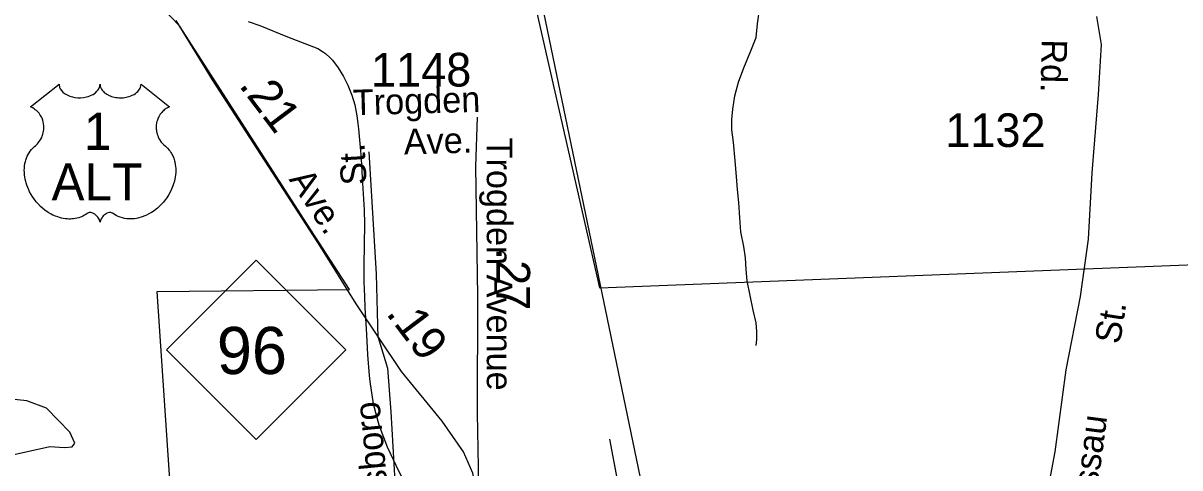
# Model space of a CAD drawing. Extents: x 2126262 to 2293712, y 749403 to 919119.
# Drawn here: x 2152197 to 2156490, y 829545 to 831196 of the extents above; entities that cross this region are included whole.
import ezdxf

# ---------------------------------------------------------------- set-up
doc = ezdxf.new("R2010")
doc.units = 0
for name, color, linetype in [('Exist Boundary Political City Limit New', 7, 'Continuous'), ('Exist Hydrographic Misc Water Feature', 7, 'Continuous'), ('Exist Hydrographic Pond Under 1500 Sq Ft', 7, 'Continuous'), ('Exist Railroad Mainline', 7, 'Continuous'), ('Exist Road Non-System Type 51', 7, 'Continuous'), ('Exist Road Non-System Type 51 Label', 7, 'Continuous'), ('Exist Road Primary NC Shield CELL', 7, 'Continuous'), ('Exist Road Primary NC Shield Number Label', 7, 'Continuous'), ('Exist Road Primary US Attributed', 7, 'Continuous'), ('Exist Road Primary US Label', 7, 'Continuous'), ('Exist Road Primary US Mileage Hundredths English Label', 7, 'Continuous'), ('Exist Road Primary US Shield CELL', 7, 'Continuous'), ('Exist Road Primary US Shield Number Label', 7, 'Continuous'), ('Exist Road Secondary Mileage Hundredths English Label', 7, 'Continuous'), ('Exist Road Secondary Type 51 Attributed', 7, 'Continuous'), ('Exist Road Secondary Type 51 Label', 7, 'Continuous'), ('Exist Road Secondary Type 51 Number Label', 7, 'Continuous'), ('Map Preparation Boundary City Limit Buffer Line', 7, 'Continuous')]:
    doc.layers.add(name, color=color, linetype=linetype)

msp = doc.modelspace()

# ---------------------------------------------------------------- linework, layer by layer
at = {"layer": 'Exist Boundary Political City Limit New'}
for points in [[(2153914.5, 832061.1), (2154336.2, 830213.6), (2156611.8, 830301.9), (2156864.5, 826396)], [(2152602.5, 827929.4), (2152838, 827985.8), (2152766.8, 829114.4), (2152693.8, 830199.1), (2153408, 830206.8), (2153250.2, 830449.8), (2152776.5, 831185.2), (2152645.8, 831322.7)]]:
    msp.add_lwpolyline(points, dxfattribs=at)
at = {"layer": 'Exist Hydrographic Misc Water Feature'}
for points in [[(2154917.4, 829998.9), (2154919, 830020.9), (2154919, 830050.9), (2154916.7, 830082.9), (2154906.5, 830130.8), (2154894.4, 830184.7), (2154883.7, 830238.7), (2154879.6, 830280.6), (2154877.4, 830324.6), (2154871, 830366.6), (2154860.8, 830420.5), (2154856.5, 830472.5), (2154852.4, 830530.5), (2154848.1, 830578.4), (2154843.7, 830626.4), (2154839.2, 830684.3), (2154833.1, 830754.3), (2154826.7, 830800.2), (2154826.5, 830838.2), (2154830.2, 830876.3), (2154838, 830926.3), (2154851.7, 830976.3), (2154871.2, 831030.4), (2154897.1, 831092.5), (2154916.7, 831142.6), (2154922.5, 831192.7), (2154930.1, 831254.7)], [(2153031.3, 831201.9), (2153075.4, 831187.4), (2153177.5, 831144.9), (2153290.3, 831101.4), (2153311, 831088.2)], [(2153031.3, 831201.9), (2153075.4, 831187.4), (2153177.5, 831144.9), (2153290.3, 831101.4), (2153311, 831088.2)], [(2153311, 831088.2), (2153319.2, 831082.9), (2153336, 831067)], [(2153311, 831088.2), (2153319.2, 831082.9), (2153336, 831067)], [(2153336, 831067), (2153344.6, 831058.8), (2153366.3, 831029.4), (2153385.4, 830997.5), (2153401.2, 830965), (2153416.4, 830929), (2153427.5, 830892.5), (2153435.4, 830851.5), (2153438.9, 830823.1)], [(2153336, 831067), (2153344.6, 831058.8), (2153366.3, 831029.4), (2153385.4, 830997.5), (2153401.2, 830965), (2153416.4, 830929), (2153427.5, 830892.5), (2153435.4, 830851.5), (2153438.9, 830823.1)], [(2153438.9, 830823.1), (2153441.4, 830802.9), (2153448.6, 830721.2)], [(2153438.9, 830823.1), (2153441.4, 830802.9), (2153448.6, 830721.2)], [(2153448.6, 830721.2), (2153451.2, 830691.7), (2153455.3, 830621.6)], [(2153448.6, 830721.2), (2153451.2, 830691.7), (2153455.3, 830621.6)], [(2153455.3, 830621.6), (2153462.3, 830502.1), (2153463.1, 830448.9), (2153461.3, 830297.1), (2153461.3, 830283.6)], [(2153455.3, 830621.6), (2153462.3, 830502.1), (2153463.1, 830448.9), (2153461.3, 830297.1), (2153461.3, 830283.6)], [(2153461.3, 830283.6), (2153461.3, 830234.9), (2153463.5, 830180.6)], [(2153461.3, 830283.6), (2153461.3, 830234.9), (2153463.5, 830180.6)], [(2153463.5, 830180.6), (2153465.4, 830139.9), (2153470.5, 830040)], [(2153463.5, 830180.6), (2153465.4, 830139.9), (2153470.5, 830040)], [(2153470.5, 830040), (2153474.4, 829964.8), (2153481.2, 829888.1)], [(2153470.5, 830040), (2153474.4, 829964.8), (2153481.2, 829888.1)], [(2153481.2, 829888.1), (2153483.2, 829864.9), (2153496.3, 829782.9)], [(2153481.2, 829888.1), (2153483.2, 829864.9), (2153496.3, 829782.9)], [(2153496.3, 829782.9), (2153517.3, 829704.3), (2153548.2, 829622.7), (2153591.3, 829530.9), (2153620, 829476.1)], [(2153496.3, 829782.9), (2153517.3, 829704.3), (2153548.2, 829622.7), (2153591.3, 829530.9), (2153620, 829476.1)]]:
    msp.add_lwpolyline(points, dxfattribs=at)
at = {"layer": 'Exist Hydrographic Pond Under 1500 Sq Ft'}
msp.add_lwpolyline([(2151770.2, 829665.6), (2151771.2, 829600.7), (2151777.6, 829571.5), (2151791.4, 829553.8), (2151830.8, 829547.9), (2151884, 829547.9), (2152157.7, 829593.2), (2152295.6, 829624.7), (2152350.7, 829620.8), (2152378.3, 829622.8), (2152388.2, 829636.6), (2152370.4, 829677.9), (2152283.8, 829766.6), (2152210.9, 829794.2), (2152094.7, 829806), (2151945, 829839.5), (2151868.2, 829821.8), (2151817, 829813.9), (2151791.4, 829810), (2151777.6, 829802.1), (2151765.8, 829772.5), (2151770.2, 829665.6)], dxfattribs=at)
at = {"layer": 'Exist Railroad Mainline'}
msp.add_lwpolyline([(2153811.5, 832603.7), (2153916.7, 832281.3), (2153928.1, 832203.5), (2154081.3, 831464.6), (2155457.3, 824828.4), (2155457.3, 824828.4), (2155482, 824689.4), (2155494.5, 824619), (2155492.8, 824605), (2155538.8, 824353.7), (2155547.3, 824199.9)], dxfattribs=at)
at = {"layer": 'Exist Road Non-System Type 51'}
for points in [[(2153514.4, 830028.6), (2153508, 830263.6), (2153481.4, 830718)], [(2153514.4, 830028.6), (2153549.3, 829914.6), (2153561.8, 829752.6), (2153575.8, 829495.3), (2153600.9, 829230)], [(2154448.7, 829287.9), (2154401.9, 829500.8), (2154374.1, 829650.9)]]:
    msp.add_lwpolyline(points, dxfattribs=at)
at = {"layer": 'Exist Road Primary NC Shield CELL'}
msp.add_lwpolyline([(2152728.5, 829982.7), (2153061.5, 830315.7), (2153394.5, 829982.7), (2153061.5, 829649.7)], close=True, dxfattribs=at)
at = {"layer": 'Exist Road Primary US Attributed'}
msp.add_lwpolyline([(2153889.5, 829414), (2153865.8, 829525.7), (2153831, 829603.9), (2153751.5, 829717.9), (2153600.8, 829902.3), (2153432.1, 830154.3), (2153301.6, 830364.4), (2152899, 830985.6), (2152764.3, 831205.6)], dxfattribs=at)
at = {"layer": 'Exist Road Primary US Shield CELL'}
msp.add_lwpolyline([(2152330, 830969.4), (2152330.3, 830965), (2152331.3, 830959.8), (2152332.2, 830957.1), (2152334.6, 830952), (2152338.6, 830945.9), (2152344.2, 830939.9), (2152350.6, 830934.7), (2152354.8, 830931.9), (2152362.1, 830928), (2152370.3, 830924.6), (2152379.5, 830921.9), (2152388.8, 830920.1), (2152399.1, 830918.9), (2152409.2, 830918.7), (2152420.1, 830919.5), (2152432.1, 830921.9), (2152437.7, 830923.3), (2152443.9, 830925.5), (2152449.7, 830927.8), (2152456.1, 830931.2), (2152461.1, 830934.5), (2152465.1, 830937.4), (2152470.8, 830942.8), (2152475.3, 830948.4), (2152477.1, 830951.5), (2152478.8, 830954.5), (2152481, 830960.9), (2152481.6, 830963.8), (2152482.1, 830969.6), (2152482.4, 830964.7), (2152483, 830961.6), (2152483.8, 830958.6), (2152485, 830955.4), (2152487.3, 830950.9), (2152489.8, 830947.1), (2152494.5, 830941.5), (2152497.5, 830938.8), (2152500.2, 830936.6), (2152507.4, 830931.6), (2152515.8, 830927.3), (2152520, 830925.5), (2152524.3, 830924), (2152529.6, 830922.4), (2152535.2, 830921.1), (2152540.8, 830920.1), (2152546.4, 830919.3), (2152552.2, 830918.9), (2152556.9, 830918.7), (2152562.7, 830918.8), (2152568, 830919.1), (2152573.5, 830919.7), (2152579.5, 830920.7), (2152584.3, 830921.8), (2152590.7, 830923.5), (2152596.5, 830925.6), (2152601.6, 830927.8), (2152608.2, 830931.2), (2152613.5, 830934.6), (2152617.4, 830937.7), (2152622, 830942), (2152626.4, 830947.1), (2152629, 830950.8), (2152630.8, 830954.6), (2152632.5, 830958.6), (2152633.6, 830962.9), (2152634.1, 830966.6), (2152634.2, 830969.8), (2152740.4, 830885.1), (2152737.9, 830884.1), (2152732.2, 830881.3), (2152727.6, 830878.6), (2152720.3, 830873.5), (2152717.1, 830870.6), (2152714, 830867.7), (2152711.1, 830864.5), (2152708.6, 830861.6), (2152705.5, 830857.3), (2152702.7, 830853), (2152700, 830848.3), (2152698.1, 830844.3), (2152694.8, 830835.7), (2152693.2, 830830.3), (2152692.2, 830825.7), (2152691, 830816.2), (2152690.6, 830811.7), (2152690.6, 830807.3), (2152690.9, 830802.6), (2152691.3, 830798), (2152692.2, 830793.3), (2152692.9, 830789.2), (2152694.2, 830784.1), (2152696.1, 830778.2), (2152698.4, 830772.5), (2152703.3, 830763.2), (2152709.5, 830753.8), (2152714, 830748.5), (2152718.4, 830744), (2152724.9, 830738.5), (2152728.5, 830735.4), (2152732.6, 830731.3), (2152739.2, 830723.6), (2152741.9, 830719.9), (2152744.7, 830715.8), (2152747.2, 830711.6), (2152749.7, 830707.1), (2152751.7, 830703.1), (2152755.4, 830694), (2152758.1, 830685.2), (2152759.4, 830680.5), (2152761.4, 830670.1), (2152762.1, 830665), (2152763, 830654.8), (2152763, 830642.5), (2152762, 830630.8), (2152759.8, 830617.2), (2152758, 830609), (2152755.2, 830599.5), (2152752.5, 830591.3), (2152747.7, 830579.2), (2152743.4, 830570.4), (2152737.8, 830560.1), (2152734, 830553.9), (2152729.5, 830547.2), (2152723.9, 830539.6), (2152717.4, 830531.4), (2152709.5, 830522.8), (2152703.2, 830516.4), (2152694.9, 830509), (2152689.9, 830504.9), (2152682.7, 830499.5), (2152672.9, 830493), (2152663.3, 830487.4), (2152655.1, 830483.2), (2152647.8, 830480), (2152638.4, 830476.4), (2152622.7, 830472.1), (2152617, 830470.9), (2152610.2, 830469.9), (2152603.8, 830469.3), (2152597.7, 830468.9), (2152589.4, 830468.9), (2152581.2, 830469.5), (2152573.4, 830470.7), (2152565.3, 830472.4), (2152556.8, 830474.9), (2152549.1, 830477.9), (2152541.4, 830481.7), (2152528.2, 830490), (2152524.4, 830492), (2152522.3, 830492.6), (2152517.2, 830492.8), (2152512.4, 830491.8), (2152507.5, 830489.9), (2152504.6, 830488.3), (2152500.7, 830485.7), (2152497.6, 830483.3), (2152494, 830479.9), (2152491.5, 830477), (2152489.6, 830474.7), (2152485.9, 830468.9), (2152484.6, 830466.1), (2152483.2, 830462.6), (2152482, 830457.3), (2152480.3, 830463.9), (2152478.3, 830468.3), (2152476.1, 830472.1), (2152473.7, 830475.4), (2152470, 830479.7), (2152466.7, 830482.9), (2152462.7, 830486.2), (2152458.4, 830488.7), (2152455, 830490.5), (2152451.9, 830491.7), (2152448, 830492.6), (2152444.9, 830492.9), (2152442.3, 830492.8), (2152438.8, 830492), (2152434, 830488.6), (2152429.4, 830485.4), (2152424.5, 830482.3), (2152418.6, 830479.2), (2152414.2, 830477.2), (2152409.1, 830475.2), (2152403.1, 830473.2), (2152396.5, 830471.5), (2152389.8, 830470.2), (2152383.9, 830469.2), (2152377.6, 830468.7), (2152371.9, 830468.5), (2152365.9, 830468.5), (2152360.3, 830469), (2152353.8, 830469.5), (2152345.8, 830470.7), (2152339.2, 830472.2), (2152332.1, 830474.1), (2152324.9, 830476.4), (2152317.2, 830479.3), (2152307.5, 830483.5), (2152300.8, 830487), (2152290.2, 830493.1), (2152277.8, 830501.7), (2152268.4, 830509.3), (2152261.5, 830515.5), (2152251.4, 830525.8), (2152245.5, 830532.5), (2152236.2, 830544.6), (2152230.2, 830553.3), (2152226.3, 830559.7), (2152220.7, 830570), (2152217.6, 830576.5), (2152213.6, 830585.9), (2152210.4, 830594.5), (2152207.8, 830602.7), (2152206.3, 830607.9), (2152204.3, 830617), (2152203.1, 830623.4), (2152201.9, 830632.3), (2152201.3, 830641.7), (2152201.1, 830650.3), (2152201.4, 830657.4), (2152202.2, 830665.8), (2152203.6, 830674.6), (2152205.3, 830682.2), (2152206.8, 830687.7), (2152209.1, 830694.3), (2152212.1, 830701.7), (2152215.6, 830708.7), (2152218.9, 830714.6), (2152223.1, 830720.9), (2152227.3, 830726.2), (2152232.7, 830732.1), (2152238.4, 830737.5), (2152243.5, 830741.7), (2152249.7, 830747.7), (2152252.9, 830751.4), (2152256.7, 830756.5), (2152259.8, 830761.2), (2152262.3, 830765.4), (2152265.5, 830771.6), (2152267.5, 830776.2), (2152269.9, 830783.4), (2152271.1, 830788.4), (2152272.4, 830794.9), (2152273.2, 830801), (2152273.5, 830808.6), (2152273.3, 830814.9), (2152272.5, 830822.2), (2152271.1, 830829.2), (2152269.5, 830835.4), (2152266.8, 830842.4), (2152264.4, 830847.6), (2152260.3, 830854.5), (2152255.8, 830861), (2152251.1, 830866.3), (2152246.4, 830871), (2152241.9, 830874.5), (2152237.6, 830877.6), (2152232.2, 830880.9), (2152227, 830883.4), (2152223.7, 830884.8)], close=True, dxfattribs=at)
at = {"layer": 'Exist Road Secondary Type 51 Attributed'}
for points in [[(2155987.8, 828437.4), (2155985, 828620.3), (2155986.4, 828776.3), (2155989.1, 828878.2), (2155989.2, 829153.9), (2155994, 829364.9), (2155994.8, 829433.8), (2156026.2, 829604.7), (2156068, 829909.1), (2156121, 830180.4), (2156150.3, 830394), (2156164.3, 830640.1), (2156188, 830930.5), (2156199.3, 831116.6), (2156181.2, 831220)], [(2153889.5, 829414), (2153882.5, 829748.3), (2153883.9, 830182.8), (2153876.9, 830664), (2153882.5, 830846.4)]]:
    msp.add_lwpolyline(points, dxfattribs=at)
at = {"layer": 'Map Preparation Boundary City Limit Buffer Line'}
for points in [[(2153914.5, 832061.1), (2154336.2, 830213.6), (2156611.8, 830301.9), (2156864.5, 826396)], [(2152602.5, 827929.4), (2152838, 827985.8), (2152766.8, 829114.4), (2152693.8, 830199.1), (2153408, 830206.8), (2153250.2, 830449.8), (2152776.5, 831185.2), (2152645.8, 831322.7)]]:
    msp.add_lwpolyline(points, dxfattribs=at)

# ---------------------------------------------------------------- texts
at = {"layer": 'Exist Road Non-System Type 51 Label'}
for s, rotation, p in [('Trogden', 1.6193, (2153421.4, 830853.4)), ('Ave.', 1.6193, (2153610.5, 830708)), ('St.', 93.1857, (2153471.7, 830597)), ('Hillsboro', 95.4582, (2153565.8, 829302.7))]:
    msp.add_text(s, height=95, rotation=rotation, dxfattribs=at).set_placement(p)
at = {"layer": 'Exist Road Primary NC Shield Number Label'}
msp.add_text('96', height=175, dxfattribs=at).set_placement((2152915.6, 829893))
at = {"layer": 'Exist Road Primary US Label'}
msp.add_text('Ave.', height=95, rotation=303.4133, dxfattribs=at).set_placement((2153181.3, 830615.6))
at = {"layer": 'Exist Road Primary US Mileage Hundredths English Label'}
for s, p in [('.21', (2152994.9, 830964.3)), ('.19', (2153540.9, 830118))]:
    msp.add_text(s, height=125, rotation=307.0636, dxfattribs=at).set_placement(p)
at = {"layer": 'Exist Road Primary US Shield Number Label'}
for s, p in [('1', (2152422.6, 830725.4)), ('ALT', (2152301.9, 830537.4))]:
    msp.add_text(s, height=137.5, dxfattribs=at).set_placement(p)
at = {"layer": 'Exist Road Secondary Mileage Hundredths English Label'}
msp.add_text('.27', height=125, rotation=269.814, dxfattribs=at).set_placement((2153953.4, 830362.9))
at = {"layer": 'Exist Road Secondary Type 51 Label'}
for s, rotation, p in [('Rd.', 268.9568, (2155976.6, 831136.4)), ('Trogden Avenue', 270, (2153917.5, 830770.7)), ('St.', 81.0114, (2156267.1, 830001.5)), ('Nassau', 82.447, (2156163.3, 829308))]:
    msp.add_text(s, height=95, rotation=rotation, dxfattribs=at).set_placement(p)
at = {"layer": 'Exist Road Secondary Type 51 Number Label'}
for s, p in [('1148', (2153487.9, 830960.5)), ('1132', (2155619.1, 830735.9))]:
    msp.add_text(s, height=125, dxfattribs=at).set_placement(p)

doc.saveas('drawing.dxf')
